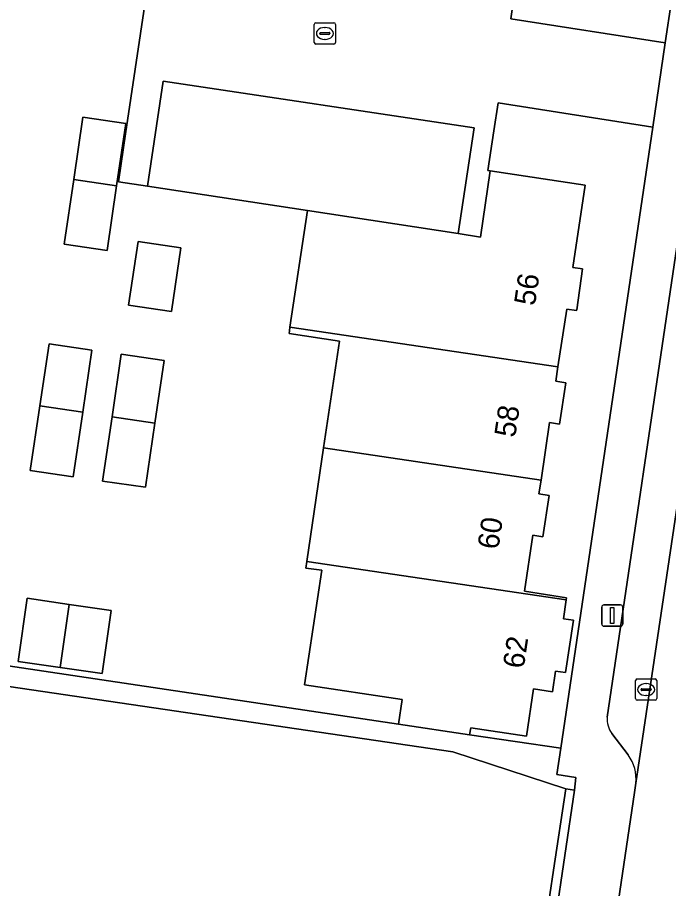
# Model space of a CAD drawing. Extents: x 164148 to 165261, y 382513 to 383432.
# Drawn here: x 164356.26 to 164386.93, y 382884.21 to 382925.26 of the extents above; entities that cross this region are included whole.
import ezdxf

# ---------------------------------------------------------------- set-up
doc = ezdxf.new("R2010")
doc.units = 0
for name, color, linetype in [('IMGEO_Erf', 7, 'Continuous'), ('IMGEO_Greppel_droge_sloot', 7, 'Continuous'), ('IMGEO_Groenvoorziening', 7, 'Continuous'), ('IMGEO_Kolk', 7, 'Continuous'), ('IMGEO_Lichtmast', 7, 'Continuous'), ('IMGEO_Muur', 7, 'Continuous'), ('IMGEO_Pand', 7, 'Continuous'), ('IMGEO_Pand_nummerreeks', 7, 'Continuous'), ('IMGEO_Parkeervlak_open', 7, 'Continuous'), ('IMGEO_Rijbaan_lokaal_open', 7, 'Continuous'), ('IMGEO_Voetpad_open', 7, 'Continuous')]:
    doc.layers.add(name, color=color, linetype=linetype)

msp = doc.modelspace()

# ---------------------------------------------------------------- linework, layer by layer
at = {"layer": 'IMGEO_Erf'}
for points in [[(164387.199, 382942.18), (164386.727, 382942.253), (164386.664, 382941.829), (164386.219, 382938.852), (164386.687, 382938.775), (164386.39, 382936.832), (164385.928, 382936.908), (164385.865, 382936.486), (164385.421, 382933.514), (164385.888, 382933.446), (164385.59, 382931.503), (164385.131, 382931.573), (164384.551, 382927.693), (164380.072, 382928.372), (164379.973, 382928.387), (164379.674, 382926.423), (164379.499, 382925.189), (164386.768, 382924.065), (164387.061, 382926.045)], [(164342.146, 382896.75), (164374.206, 382891.958), (164374.382, 382893.116), (164369.782, 382893.81), (164370.598, 382899.206), (164369.836, 382899.311), (164369.883, 382899.628), (164370.679, 382904.972), (164371.429, 382910.007), (164369.052, 382910.366), (164369.071, 382910.492), (164369.096, 382910.658), (164369.928, 382916.155), (164362.394, 382917.305), (164361.014, 382917.516), (164361.351, 382919.771), (164363.474, 382933.973)]]:
    msp.add_lwpolyline(points, dxfattribs=at)
for points in [[(164386.181, 382920.095), (164378.902, 382921.233), (164378.704, 382919.912), (164378.422, 382918.043), (164378.531, 382918.027), (164383.005, 382917.362), (164382.422, 382913.479), (164382.875, 382913.408), (164382.602, 382911.482), (164382.596, 382911.446), (164382.128, 382911.516), (164381.719, 382908.79), (164381.618, 382908.116), (164382.088, 382908.046), (164381.796, 382906.098), (164381.326, 382906.168), (164380.919, 382903.456), (164380.822, 382902.806), (164381.297, 382902.735), (164381.005, 382900.787), (164380.53, 382900.858), (164380.134, 382898.216), (164382.123, 382897.915), (164382.109, 382897.819), (164381.975, 382896.927), (164382.449, 382896.853), (164382.08, 382894.388), (164381.605, 382894.46), (164381.458, 382893.481), (164380.561, 382893.614), (164380.232, 382891.398), (164377.608, 382891.787), (164377.559, 382891.461), (164381.848, 382890.825)], [(164361.369, 382920.263), (164360.934, 382917.328), (164360.483, 382914.282), (164358.466, 382914.581), (164358.915, 382917.627), (164359.347, 382920.563)], [(164363.96, 382914.408), (164363.517, 382911.404), (164361.495, 382911.705), (164361.942, 382914.708)], [(164359.768, 382909.585), (164359.335, 382906.651), (164358.887, 382903.618), (164356.864, 382903.917), (164357.313, 382906.95), (164357.748, 382909.883)], [(164363.167, 382909.094), (164362.734, 382906.147), (164362.289, 382903.118), (164360.272, 382903.414), (164360.716, 382906.446), (164361.148, 382909.39)], [(164360.681, 382897.315), (164360.25, 382894.343), (164358.271, 382894.63), (164356.292, 382894.916), (164356.722, 382897.888), (164358.701, 382897.602)]]:
    msp.add_lwpolyline(points, close=True, dxfattribs=at)
at = {"layer": 'IMGEO_Greppel_droge_sloot'}
msp.add_lwpolyline([(164382.088, 382888.915), (164376.77, 382890.66), (164335.456, 382896.737), (164333.916, 382896.025), (164333.345, 382892.225), (164332.994, 382889.886), (164332.715, 382888.027), (164331.978, 382883.118), (164337.42, 382885.111), (164342.387, 382883.177), (164346.526, 382880.937), (164353.204, 382878.84), (164360.537, 382880.438), (164366.224, 382880.38), (164369.317, 382880.03), (164371.665, 382878.387), (164373.755, 382876.443), (164376.26, 382874.804), (164380.157, 382875.992), (164380.851, 382880.641), (164381.166, 382882.748), (164381.513, 382885.072)], close=True, dxfattribs=at)
at = {"layer": 'IMGEO_Groenvoorziening'}
msp.add_lwpolyline([(164377.559, 382891.461), (164374.206, 382891.958), (164342.146, 382896.75), (164338.789, 382897.217), (164334.637, 382897.794), (164334.647, 382897.854), (164333.774, 382897.977), (164333.508, 382896.089), (164333.916, 382896.025), (164335.456, 382896.737), (164376.77, 382890.66), (164382.088, 382888.915), (164382.495, 382888.849), (164382.566, 382889.449), (164381.663, 382889.579), (164381.848, 382890.825)], close=True, dxfattribs=at)
at = {"layer": 'IMGEO_Kolk'}
for p, q in [((164370.313, 382925.005), (164371.165, 382925.005)), ((164370.238, 382924.079), (164370.238, 382924.931)), ((164370.726, 382924.785), (164370.751, 382924.785)), ((164371.239, 382924.931), (164371.239, 382924.079)), ((164370.497, 382924.499), (164370.497, 382924.511)), ((164370.935, 382924.462), (164370.537, 382924.462)), ((164370.54, 382924.548), (164370.938, 382924.548)), ((164370.749, 382924.225), (164370.724, 382924.225)), ((164370.981, 382924.511), (164370.981, 382924.499)), ((164371.165, 382924.005), (164370.313, 382924.005)), ((164385.371, 382893.16), (164385.371, 382894.012)), ((164385.446, 382894.086), (164386.298, 382894.086)), ((164385.859, 382893.866), (164385.884, 382893.866)), ((164386.372, 382894.012), (164386.372, 382893.16)), ((164385.63, 382893.58), (164385.63, 382893.592)), ((164386.068, 382893.543), (164385.67, 382893.543)), ((164385.673, 382893.629), (164386.071, 382893.629)), ((164386.114, 382893.592), (164386.114, 382893.58)), ((164386.298, 382893.086), (164385.446, 382893.086)), ((164385.882, 382893.306), (164385.857, 382893.306))]:
    msp.add_line(p, q, dxfattribs=at)
for points in [[(164370.313, 382925.005), (164371.165, 382925.005)], [(164370.238, 382924.079), (164370.238, 382924.931)], [(164371.239, 382924.931), (164371.239, 382924.079)], [(164371.165, 382924.005), (164370.313, 382924.005)], [(164385.371, 382893.16), (164385.371, 382894.012)], [(164385.446, 382894.086), (164386.298, 382894.086)], [(164386.372, 382894.012), (164386.372, 382893.16)], [(164386.298, 382893.086), (164385.446, 382893.086)]]:
    msp.add_lwpolyline(points, dxfattribs=at)
for centre, radius, start, end in [((164370.315, 382924.929), 0.0765, 91.552, 178.448), ((164370.315, 382924.929), 0.0765, 91.552, 178.448), ((164371.163, 382924.929), 0.0765, 1.552, 88.448), ((164371.163, 382924.929), 0.0765, 1.552, 88.448), ((164370.537, 382924.508), 0.0403, 85.8775, 175.7526), ((164370.534, 382924.498), 0.0366, 178.938, 274.7102), ((164370.938, 382924.505), 0.043, 264.8664, 352.4533), ((164370.942, 382924.51), 0.0386, 1.7309, 96.639), ((164370.315, 382924.081), 0.0765, 181.552, 268.448), ((164370.315, 382924.081), 0.0765, 181.552, 268.448), ((164371.163, 382924.081), 0.0765, 271.552, 358.448), ((164371.163, 382924.081), 0.0765, 271.552, 358.448), ((164385.448, 382894.01), 0.0765, 91.552, 178.448), ((164385.448, 382894.01), 0.0765, 91.552, 178.448), ((164386.296, 382894.01), 0.0765, 1.552, 88.448), ((164386.296, 382894.01), 0.0765, 1.552, 88.448), ((164385.67, 382893.589), 0.0403, 85.8775, 175.7526), ((164385.667, 382893.579), 0.0366, 178.938, 274.7102), ((164386.071, 382893.586), 0.043, 264.8664, 352.4533), ((164386.075, 382893.591), 0.0386, 1.7309, 96.639), ((164385.448, 382893.162), 0.0765, 181.552, 268.448), ((164385.448, 382893.162), 0.0765, 181.552, 268.448), ((164386.296, 382893.162), 0.0765, 271.552, 358.448), ((164386.296, 382893.162), 0.0765, 271.552, 358.448)]:
    msp.add_arc(centre, radius, start, end, dxfattribs=at)
for centre, major_axis, ratio, start_param, end_param in [((164370.725, 382924.505), (-0.387, 0.002), 0.722429, 4.712389, 7.853982), ((164370.75, 382924.505), (-0.39, 0.002), 0.717154, 1.570796, 4.712389), ((164385.858, 382893.586), (-0.387, 0.002), 0.722429, 4.712389, 7.853982), ((164385.883, 382893.586), (-0.39, 0.002), 0.717154, 1.570796, 4.712389)]:
    msp.add_ellipse(centre, major_axis=major_axis, ratio=ratio, start_param=start_param, end_param=end_param, dxfattribs=at)
at = {"layer": 'IMGEO_Lichtmast'}
for p, q in [((164383.779, 382896.672), (164383.779, 382897.472)), ((164383.779, 382897.472), (164383.779, 382896.672)), ((164383.879, 382897.572), (164384.669, 382897.572)), ((164384.669, 382897.572), (164383.879, 382897.572)), ((164384.769, 382897.472), (164384.769, 382896.672)), ((164384.769, 382896.672), (164384.769, 382897.472)), ((164384.669, 382896.572), (164383.879, 382896.572)), ((164383.879, 382896.572), (164384.669, 382896.572))]:
    msp.add_line(p, q, dxfattribs=at)
msp.add_lwpolyline([(164384.199, 382897.447), (164384.349, 382897.447), (164384.349, 382896.697), (164384.199, 382896.697), (164384.199, 382897.447)], dxfattribs=at)
for centre, start, end in [((164383.879, 382897.472), 90, 180), ((164383.879, 382897.472), 90, 180), ((164384.669, 382897.472), 0, 90), ((164384.669, 382897.472), 360, 90), ((164383.879, 382896.672), 180, 270), ((164383.879, 382896.672), 180, 270), ((164384.669, 382896.672), 270, 0), ((164384.669, 382896.672), 270, 0)]:
    msp.add_arc(centre, 0.1, start, end, dxfattribs=at)
at = {"layer": 'IMGEO_Muur'}
msp.add_lwpolyline([(164374.206, 382891.958), (164342.146, 382896.75)], dxfattribs=at)
msp.add_lwpolyline([(164381.579, 382882.687), (164382.495, 382888.849), (164382.088, 382888.915), (164381.513, 382885.072), (164381.166, 382882.748), (164380.851, 382880.641), (164380.157, 382875.992), (164380.573, 382875.921)], close=True, dxfattribs=at)
at = {"layer": 'IMGEO_Pand'}
for points in [[(164361.369, 382920.263), (164359.347, 382920.563), (164358.915, 382917.627), (164360.934, 382917.328)], [(164382.875, 382913.408), (164382.422, 382913.479), (164383.005, 382917.362), (164378.531, 382918.027), (164378.064, 382914.912), (164377.017, 382915.072), (164369.928, 382916.155), (164369.096, 382910.658), (164381.719, 382908.79), (164382.128, 382911.516), (164382.596, 382911.446), (164382.602, 382911.482)], [(164360.934, 382917.328), (164358.915, 382917.627), (164358.466, 382914.581), (164360.483, 382914.282)], [(164363.96, 382914.408), (164361.942, 382914.708), (164361.495, 382911.705), (164363.517, 382911.404)], [(164382.088, 382908.046), (164381.618, 382908.116), (164381.719, 382908.79), (164369.096, 382910.658), (164369.071, 382910.492), (164369.052, 382910.366), (164371.429, 382910.007), (164370.679, 382904.972), (164380.919, 382903.456), (164381.326, 382906.168), (164381.796, 382906.098)], [(164359.768, 382909.585), (164357.748, 382909.883), (164357.313, 382906.95), (164359.335, 382906.651)], [(164363.167, 382909.094), (164361.148, 382909.39), (164360.716, 382906.446), (164362.734, 382906.147)], [(164359.335, 382906.651), (164357.313, 382906.95), (164356.864, 382903.917), (164358.887, 382903.618)], [(164362.734, 382906.147), (164360.716, 382906.446), (164360.272, 382903.414), (164362.289, 382903.118)], [(164380.822, 382902.806), (164380.919, 382903.456), (164370.679, 382904.972), (164369.883, 382899.628), (164382.109, 382897.819), (164382.123, 382897.915), (164380.134, 382898.216), (164380.53, 382900.858), (164381.005, 382900.787), (164381.297, 382902.735)], [(164382.449, 382896.853), (164381.975, 382896.927), (164382.109, 382897.819), (164369.883, 382899.628), (164369.836, 382899.311), (164370.598, 382899.206), (164369.782, 382893.81), (164374.382, 382893.116), (164374.206, 382891.958), (164377.559, 382891.461), (164377.608, 382891.787), (164380.232, 382891.398), (164380.561, 382893.614), (164381.458, 382893.481), (164381.605, 382894.46), (164382.08, 382894.388)], [(164358.701, 382897.602), (164356.722, 382897.888), (164356.292, 382894.916), (164358.271, 382894.63)], [(164360.681, 382897.315), (164358.701, 382897.602), (164358.271, 382894.63), (164360.25, 382894.343)]]:
    msp.add_lwpolyline(points, close=True, dxfattribs=at)
at = {"layer": 'IMGEO_Parkeervlak_open'}
msp.add_lwpolyline([(164377.768, 382920.053), (164363.127, 382922.256), (164362.394, 382917.305), (164369.928, 382916.155), (164377.017, 382915.072)], close=True, dxfattribs=at)
for points in [[(164385.388, 382889.174), (164389.603, 382917.523)], [(164387.38, 382914.874), (164384.04, 382892.287)], [(164384.25, 382891.521), (164385.021, 382890.506)]]:
    msp.add_lwpolyline(points, dxfattribs=at)
for centre, radius, start, end in [((164385.153, 382892.18), 1.118, 174.5292, 216.1328), ((164383.517, 382889.375), 1.882, 353.8663, 36.9421)]:
    msp.add_arc(centre, radius, start, end, dxfattribs=at)
at = {"layer": 'IMGEO_Rijbaan_lokaal_open'}
for points in [[(164400.876, 382959.355), (164401.178, 382961.379), (164396.236, 382962.229), (164391.231, 382928.476), (164390.809, 382925.629), (164389.611, 382917.573), (164389.603, 382917.523), (164385.388, 382889.174), (164385.323, 382888.74), (164383.455, 382876.131), (164383.436, 382876.014), (164388.332, 382875.297), (164388.347, 382875.416), (164390.241, 382888.06), (164390.296, 382888.433), (164395.748, 382925.028)], [(164379.674, 382926.423), (164379.973, 382928.387), (164380.072, 382928.372), (164380.527, 382931.483), (164379.522, 382931.636), (164378.755, 382926.565), (164364.119, 382928.814), (164364.842, 382933.776), (164363.474, 382933.973), (164361.351, 382919.771), (164361.014, 382917.516), (164362.394, 382917.305), (164363.127, 382922.256), (164377.768, 382920.053), (164377.017, 382915.072), (164378.064, 382914.912), (164378.531, 382918.027), (164378.422, 382918.043), (164378.704, 382919.912), (164378.902, 382921.233), (164386.181, 382920.095), (164386.768, 382924.065), (164379.499, 382925.189)]]:
    msp.add_lwpolyline(points, close=True, dxfattribs=at)
at = {"layer": 'IMGEO_Voetpad_open'}
for points in [[(164331.556, 382883.173), (164332.58, 382889.948), (164333.508, 382896.089), (164333.774, 382897.977), (164334.647, 382897.854), (164343.748, 382959.071), (164346.307, 382976.27), (164346.897, 382980.236), (164351.168, 383008.935), (164353.396, 383008.625), (164396.201, 383002.256), (164398.318, 383001.938), (164394.057, 382973.175), (164393.467, 382969.194), (164387.902, 382931.724), (164387.061, 382926.045), (164386.768, 382924.065), (164386.181, 382920.095), (164381.848, 382890.825), (164381.663, 382889.579), (164382.566, 382889.449), (164382.495, 382888.849), (164381.579, 382882.687), (164380.573, 382875.921)], [(164384.04, 382892.287), (164387.38, 382914.874)], [(164385.021, 382890.506), (164384.25, 382891.521)], [(164383.309, 382875.221), (164383.436, 382876.014), (164383.455, 382876.131), (164385.323, 382888.74), (164385.388, 382889.174)]]:
    msp.add_lwpolyline(points, dxfattribs=at)
for centre, radius, start, end in [((164385.153, 382892.18), 1.118, 174.5292, 216.1328), ((164383.517, 382889.375), 1.882, 353.8663, 36.9421)]:
    msp.add_arc(centre, radius, start, end, dxfattribs=at)

# ---------------------------------------------------------------- texts
at = {"layer": 'IMGEO_Pand_nummerreeks'}
for s, rotation, p in [('56', 81.4689, (164380.63, 382911.643)), ('58', 81.4746, (164379.699, 382905.433)), ('60', 81.4746, (164378.908, 382900.155)), ('62', 81.4631, (164380.101, 382894.542))]:
    msp.add_text(s, height=1, rotation=rotation, dxfattribs=at).set_placement(p)

doc.saveas('drawing.dxf')
